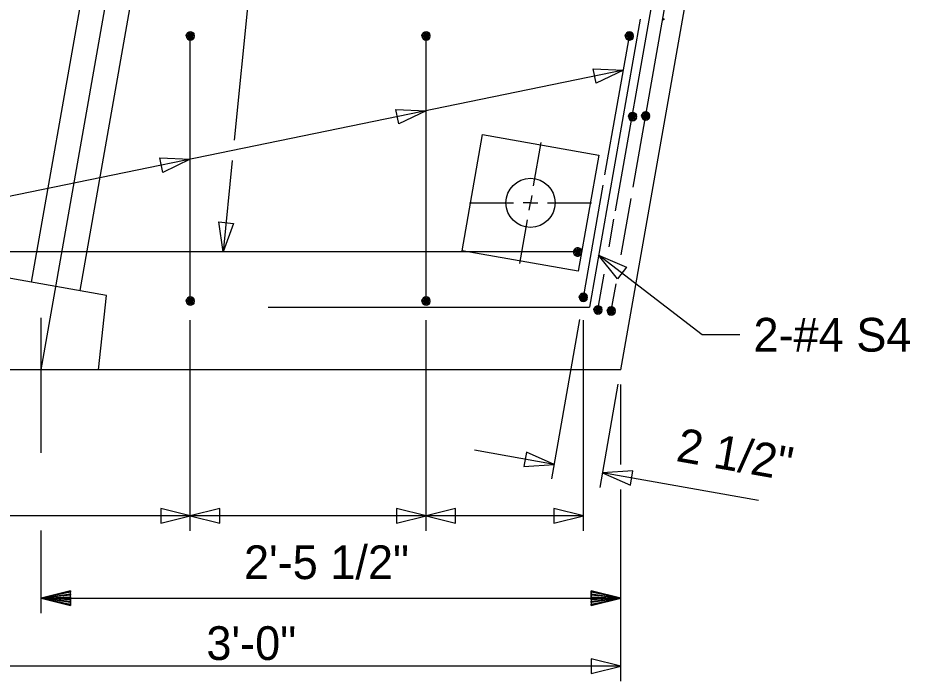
# Model space of a CAD drawing. Extents: x -408 to -23, y -15 to 117.
# Drawn here: x -92.937 to -89.153, y 40.166 to 42.979 of the extents above; entities that cross this region are included whole.
import ezdxf

# ---------------------------------------------------------------- set-up
doc = ezdxf.new("R2010")
doc.units = 0
for name, color, linetype in [('Arrowhead Terminators CELL', 7, 'Continuous'), ('Dimension Lines', 7, 'Continuous'), ('Mis Center Lines', 7, 'Continuous'), ('Rebar Lines', 7, 'Continuous'), ('Sup Concrete Girder Lines', 7, 'Continuous'), ('Sup Cored Slab Unit', 7, 'Continuous'), ('Text', 7, 'Continuous')]:
    doc.layers.add(name, color=color, linetype=linetype)

msp = doc.modelspace()

# ---------------------------------------------------------------- linework, layer by layer
at = {"layer": 'Arrowhead Terminators CELL'}
for points in [[(-90.3692, 42.7573), (-90.4853, 42.7015), (-90.4979, 42.7627)], [(-91.2058, 42.5852), (-91.3219, 42.5294), (-91.3345, 42.5906)], [(-92.2058, 42.3794), (-92.3219, 42.3236), (-92.3345, 42.3848)], [(-92.0665, 41.9859), (-92.0852, 42.1134), (-92.023, 42.1072)], [(-90.4746, 41.9723), (-90.3564, 41.921), (-90.3945, 41.8714)], [(-90.6624, 41.0852), (-90.7801, 41.1377), (-90.7909, 41.0761)], [(-90.4573, 41.049), (-90.3396, 40.9965), (-90.3287, 41.0581)], [(-92.2058, 40.8667), (-92.3308, 40.898), (-92.3308, 40.8355)], [(-92.2058, 40.8667), (-92.0808, 40.8355), (-92.0808, 40.898)], [(-91.2058, 40.8667), (-91.3308, 40.898), (-91.3308, 40.8355)], [(-91.2058, 40.8667), (-91.0808, 40.8355), (-91.0808, 40.898)], [(-90.5391, 40.8667), (-90.6641, 40.898), (-90.6641, 40.8355)], [(-90.3803, 40.229), (-90.5053, 40.2603), (-90.5053, 40.1978)]]:
    msp.add_lwpolyline(points, close=True, dxfattribs=at)
at = {"layer": 'Dimension Lines'}
for p, q in [((-91.905, 43.6051), (-92.0192, 42.4603)), ((-90.7507, 42.2662), (-90.7181, 42.4508)), ((-92.0279, 42.3735), (-92.0665, 41.9859)), ((-91.0224, 42.1942), (-90.8349, 42.1942)), ((-90.6918, 42.1942), (-90.5043, 42.1942)), ((-90.8086, 41.9377), (-90.776, 42.1223)), ((-92.8386, 41.134), (-92.8386, 41.7067)), ((-92.2058, 40.8037), (-92.2058, 41.6974)), ((-91.2058, 40.8037), (-91.2058, 41.6974)), ((-90.6733, 41.0236), (-90.5541, 41.7)), ((-90.5391, 40.8037), (-90.5391, 41.6974)), ((-90.4681, 40.9875), (-90.391, 41.4253)), ((-90.3803, 41.0844), (-90.3803, 41.4234)), ((-90.6624, 41.0852), (-91.0013, 41.145)), ((-89.797, 40.9326), (-90.4573, 41.049)), ((-90.3803, 40.166), (-90.3803, 40.9785)), ((-92.2058, 40.8667), (-93.2058, 40.8667)), ((-91.2058, 40.8667), (-92.2058, 40.8667)), ((-90.5391, 40.8667), (-91.2058, 40.8667)), ((-92.8386, 40.4548), (-92.8386, 40.8042)), ((-92.8386, 40.5178), (-90.3803, 40.5178)), ((-90.3803, 40.229), (-93.3803, 40.229))]:
    msp.add_line(p, q, dxfattribs=at)
for points in [[(-90.3692, 42.7573), (-94.2479, 41.9592), (-94.3499, 41.9592)], [(-90.7578, 42.2251), (-90.7633, 42.1942), (-90.7948, 42.1943)], [(-90.7689, 42.1633), (-90.7633, 42.1942), (-90.7319, 42.1941)], [(-89.876, 41.635), (-90.0352, 41.635), (-90.4746, 41.9723)], [(-92.7136, 40.5178), (-92.7136, 40.5115), (-92.8386, 40.5178), (-92.7136, 40.5053), (-92.7136, 40.499), (-92.8386, 40.5178), (-92.7136, 40.4928), (-92.7136, 40.4865), (-92.8386, 40.5178), (-92.7136, 40.549), (-92.7136, 40.5428), (-92.8386, 40.5178), (-92.7136, 40.5365), (-92.7136, 40.5303), (-92.8386, 40.5178), (-92.7136, 40.524), (-92.7136, 40.4865), (-92.7136, 40.549), (-92.8386, 40.5178), (-92.7136, 40.4865)], [(-90.5053, 40.5178), (-90.5053, 40.524), (-90.3803, 40.5178), (-90.5053, 40.5303), (-90.5053, 40.5365), (-90.3803, 40.5178), (-90.5053, 40.5428), (-90.5053, 40.549), (-90.3803, 40.5178), (-90.5053, 40.4865), (-90.5053, 40.4928), (-90.3803, 40.5178), (-90.5053, 40.499), (-90.5053, 40.5053), (-90.3803, 40.5178), (-90.5053, 40.5115), (-90.5053, 40.549), (-90.5053, 40.4865), (-90.3803, 40.5178), (-90.5053, 40.549)]]:
    msp.add_lwpolyline(points, dxfattribs=at)
at = {"layer": 'Mis Center Lines'}
msp.add_line((-92.8386, 41.4859), (-92.3205, 44.4243), dxfattribs=at)
at = {"layer": 'Rebar Lines'}
for p, q in [((-90.4029, 42.1609), (-90.2165, 43.2181)), ((-90.3283, 42.2602), (-90.1746, 43.1323)), ((-90.2982, 42.9727), (-90.5135, 41.7515)), ((-92.2058, 41.7775), (-92.2058, 42.9025)), ((-92.2058, 42.3526), (-92.2058, 42.9025)), ((-91.2058, 41.7775), (-91.2058, 42.9025)), ((-91.2058, 42.3526), (-91.2058, 42.9025)), ((-90.4476, 42.3127), (-90.3438, 42.9015)), ((-90.5391, 41.7936), (-90.4552, 42.2694)), ((-90.3788, 41.9739), (-90.3368, 42.2123)), ((-90.4299, 42.0075), (-90.4091, 42.1254)), ((-90.5633, 41.9859), (-93.2508, 41.9859)), ((-90.477, 41.7403), (-90.4504, 41.8912)), ((-90.4208, 41.7359), (-90.4005, 41.8506)), ((-91.8758, 41.7515), (-90.5135, 41.7515))]:
    msp.add_line(p, q, dxfattribs=at)
for points in [[(-92.1882, 42.9025), (-92.1895, 42.9092), (-92.1933, 42.915), (-92.199, 42.9188), (-92.2058, 42.9201), (-92.2125, 42.9188), (-92.2183, 42.915), (-92.2221, 42.9093), (-92.2234, 42.9025), (-92.2221, 42.8958), (-92.2183, 42.8901), (-92.2126, 42.8862), (-92.2058, 42.8849), (-92.199, 42.8862), (-92.1934, 42.89), (-92.1895, 42.8957), (-92.1882, 42.9025), (-92.2058, 42.9025), (-92.2234, 42.9025), (-92.2221, 42.9093), (-92.2058, 42.9025), (-92.2183, 42.915), (-92.2125, 42.9188), (-92.2058, 42.9025), (-92.2058, 42.9201), (-92.199, 42.9188), (-92.2058, 42.9025), (-92.1933, 42.915), (-92.1895, 42.9092), (-92.2058, 42.9025), (-92.1895, 42.8957), (-92.1934, 42.89), (-92.2058, 42.9025), (-92.199, 42.8862), (-92.2058, 42.8849), (-92.2058, 42.9025), (-92.2126, 42.8862), (-92.2183, 42.8901), (-92.2058, 42.9025), (-92.2221, 42.8958)], [(-91.1882, 42.9025), (-91.1895, 42.9092), (-91.1933, 42.915), (-91.199, 42.9188), (-91.2058, 42.9201), (-91.2125, 42.9188), (-91.2183, 42.915), (-91.2221, 42.9093), (-91.2234, 42.9025), (-91.2221, 42.8958), (-91.2183, 42.8901), (-91.2126, 42.8862), (-91.2058, 42.8849), (-91.199, 42.8862), (-91.1934, 42.89), (-91.1895, 42.8957), (-91.1882, 42.9025), (-91.2058, 42.9025), (-91.2234, 42.9025), (-91.2221, 42.9093), (-91.2058, 42.9025), (-91.2183, 42.915), (-91.2125, 42.9188), (-91.2058, 42.9025), (-91.2058, 42.9201), (-91.199, 42.9188), (-91.2058, 42.9025), (-91.1933, 42.915), (-91.1895, 42.9092), (-91.2058, 42.9025), (-91.1895, 42.8957), (-91.1934, 42.89), (-91.2058, 42.9025), (-91.199, 42.8862), (-91.2058, 42.8849), (-91.2058, 42.9025), (-91.2126, 42.8862), (-91.2183, 42.8901), (-91.2058, 42.9025), (-91.2221, 42.8958)], [(-90.3262, 42.9015), (-90.3275, 42.9082), (-90.3313, 42.9139), (-90.337, 42.9178), (-90.3438, 42.9191), (-90.3505, 42.9178), (-90.3562, 42.9139), (-90.36, 42.9082), (-90.3614, 42.9015), (-90.36, 42.8948), (-90.3562, 42.889), (-90.3505, 42.8852), (-90.3438, 42.8838), (-90.337, 42.8852), (-90.3313, 42.889), (-90.3275, 42.8947), (-90.3262, 42.9015), (-90.3438, 42.9015), (-90.3614, 42.9015), (-90.36, 42.9082), (-90.3438, 42.9015), (-90.3562, 42.9139), (-90.3505, 42.9178), (-90.3438, 42.9015), (-90.3438, 42.9191), (-90.337, 42.9178), (-90.3438, 42.9015), (-90.3313, 42.9139), (-90.3275, 42.9082), (-90.3438, 42.9015), (-90.3275, 42.8947), (-90.3313, 42.889), (-90.3438, 42.9015), (-90.337, 42.8852), (-90.3438, 42.8838), (-90.3438, 42.9015), (-90.3505, 42.8852), (-90.3562, 42.889), (-90.3438, 42.9015), (-90.36, 42.8948)], [(-90.3127, 42.5604), (-90.314, 42.5671), (-90.3178, 42.5728), (-90.3235, 42.5767), (-90.3303, 42.578), (-90.337, 42.5767), (-90.3427, 42.5728), (-90.3465, 42.5671), (-90.3479, 42.5604), (-90.3465, 42.5537), (-90.3427, 42.5479), (-90.3371, 42.5441), (-90.3303, 42.5427), (-90.3235, 42.5441), (-90.3178, 42.5479), (-90.314, 42.5536), (-90.3127, 42.5604), (-90.3303, 42.5604), (-90.3479, 42.5604), (-90.3465, 42.5671), (-90.3303, 42.5604), (-90.3427, 42.5728), (-90.337, 42.5767), (-90.3303, 42.5604), (-90.3303, 42.578), (-90.3235, 42.5767), (-90.3303, 42.5604), (-90.3178, 42.5728), (-90.314, 42.5671), (-90.3303, 42.5604), (-90.314, 42.5536), (-90.3178, 42.5479), (-90.3303, 42.5604), (-90.3235, 42.5441), (-90.3303, 42.5427), (-90.3303, 42.5604), (-90.3371, 42.5441), (-90.3427, 42.5479), (-90.3303, 42.5604), (-90.3465, 42.5537)], [(-90.2574, 42.5625), (-90.2587, 42.5692), (-90.2625, 42.575), (-90.2683, 42.5788), (-90.275, 42.5801), (-90.2817, 42.5788), (-90.2875, 42.575), (-90.2913, 42.5693), (-90.2926, 42.5625), (-90.2913, 42.5558), (-90.2875, 42.5501), (-90.2818, 42.5462), (-90.275, 42.5449), (-90.2683, 42.5462), (-90.2626, 42.55), (-90.2587, 42.5557), (-90.2574, 42.5625), (-90.275, 42.5625), (-90.2926, 42.5625), (-90.2913, 42.5693), (-90.275, 42.5625), (-90.2875, 42.575), (-90.2817, 42.5788), (-90.275, 42.5625), (-90.275, 42.5801), (-90.2683, 42.5788), (-90.275, 42.5625), (-90.2625, 42.575), (-90.2587, 42.5692), (-90.275, 42.5625), (-90.2587, 42.5557), (-90.2626, 42.55), (-90.275, 42.5625), (-90.2683, 42.5462), (-90.275, 42.5449), (-90.275, 42.5625), (-90.2818, 42.5462), (-90.2875, 42.5501), (-90.275, 42.5625), (-90.2913, 42.5558)], [(-90.546, 41.9828), (-90.5462, 41.9897), (-90.5489, 41.996), (-90.5539, 42.0008), (-90.5603, 42.0032), (-90.5671, 42.0031), (-90.5734, 42.0003), (-90.5782, 41.9954), (-90.5807, 41.989), (-90.5805, 41.9821), (-90.5778, 41.9758), (-90.5729, 41.971), (-90.5664, 41.9685), (-90.5595, 41.9687), (-90.5533, 41.9714), (-90.5485, 41.9764), (-90.546, 41.9828), (-90.5633, 41.9859), (-90.5807, 41.989), (-90.5782, 41.9954), (-90.5633, 41.9859), (-90.5734, 42.0003), (-90.5671, 42.0031), (-90.5633, 41.9859), (-90.5603, 42.0032), (-90.5539, 42.0008), (-90.5633, 41.9859), (-90.5489, 41.996), (-90.5462, 41.9897), (-90.5633, 41.9859), (-90.5485, 41.9764), (-90.5533, 41.9714), (-90.5633, 41.9859), (-90.5595, 41.9687), (-90.5664, 41.9685), (-90.5633, 41.9859), (-90.5729, 41.971), (-90.5778, 41.9758), (-90.5633, 41.9859), (-90.5805, 41.9821)], [(-92.1882, 41.7775), (-92.1895, 41.7842), (-92.1933, 41.79), (-92.199, 41.7938), (-92.2058, 41.7951), (-92.2125, 41.7938), (-92.2183, 41.79), (-92.2221, 41.7843), (-92.2234, 41.7775), (-92.2221, 41.7708), (-92.2183, 41.7651), (-92.2126, 41.7612), (-92.2058, 41.7599), (-92.199, 41.7612), (-92.1934, 41.765), (-92.1895, 41.7707), (-92.1882, 41.7775), (-92.2058, 41.7775), (-92.2234, 41.7775), (-92.2221, 41.7843), (-92.2058, 41.7775), (-92.2183, 41.79), (-92.2125, 41.7938), (-92.2058, 41.7775), (-92.2058, 41.7951), (-92.199, 41.7938), (-92.2058, 41.7775), (-92.1933, 41.79), (-92.1895, 41.7842), (-92.2058, 41.7775), (-92.1895, 41.7707), (-92.1934, 41.765), (-92.2058, 41.7775), (-92.199, 41.7612), (-92.2058, 41.7599), (-92.2058, 41.7775), (-92.2126, 41.7612), (-92.2183, 41.7651), (-92.2058, 41.7775), (-92.2221, 41.7708)], [(-91.1882, 41.7775), (-91.1895, 41.7842), (-91.1933, 41.79), (-91.199, 41.7938), (-91.2058, 41.7951), (-91.2125, 41.7938), (-91.2183, 41.79), (-91.2221, 41.7843), (-91.2234, 41.7775), (-91.2221, 41.7708), (-91.2183, 41.7651), (-91.2126, 41.7612), (-91.2058, 41.7599), (-91.199, 41.7612), (-91.1934, 41.765), (-91.1895, 41.7707), (-91.1882, 41.7775), (-91.2058, 41.7775), (-91.2234, 41.7775), (-91.2221, 41.7843), (-91.2058, 41.7775), (-91.2183, 41.79), (-91.2125, 41.7938), (-91.2058, 41.7775), (-91.2058, 41.7951), (-91.199, 41.7938), (-91.2058, 41.7775), (-91.1933, 41.79), (-91.1895, 41.7842), (-91.2058, 41.7775), (-91.1895, 41.7707), (-91.1934, 41.765), (-91.2058, 41.7775), (-91.199, 41.7612), (-91.2058, 41.7599), (-91.2058, 41.7775), (-91.2126, 41.7612), (-91.2183, 41.7651), (-91.2058, 41.7775), (-91.2221, 41.7708)], [(-90.5215, 41.7936), (-90.5228, 41.8003), (-90.5266, 41.806), (-90.5324, 41.8099), (-90.5391, 41.8112), (-90.5459, 41.8099), (-90.5516, 41.806), (-90.5554, 41.8003), (-90.5567, 41.7936), (-90.5554, 41.7868), (-90.5516, 41.7811), (-90.5459, 41.7773), (-90.5391, 41.7759), (-90.5324, 41.7773), (-90.5267, 41.7811), (-90.5228, 41.7868), (-90.5215, 41.7936), (-90.5391, 41.7936), (-90.5567, 41.7936), (-90.5554, 41.8003), (-90.5391, 41.7936), (-90.5516, 41.806), (-90.5459, 41.8099), (-90.5391, 41.7936), (-90.5391, 41.8112), (-90.5324, 41.8099), (-90.5391, 41.7936), (-90.5266, 41.806), (-90.5228, 41.8003), (-90.5391, 41.7936), (-90.5228, 41.7868), (-90.5267, 41.7811), (-90.5391, 41.7936), (-90.5324, 41.7773), (-90.5391, 41.7759), (-90.5391, 41.7936), (-90.5459, 41.7773), (-90.5516, 41.7811), (-90.5391, 41.7936), (-90.5554, 41.7868)], [(-90.4594, 41.7403), (-90.4607, 41.747), (-90.4645, 41.7528), (-90.4702, 41.7566), (-90.477, 41.7579), (-90.4837, 41.7566), (-90.4895, 41.7528), (-90.4933, 41.7471), (-90.4946, 41.7403), (-90.4933, 41.7336), (-90.4895, 41.7279), (-90.4838, 41.724), (-90.477, 41.7227), (-90.4702, 41.724), (-90.4646, 41.7278), (-90.4607, 41.7336), (-90.4594, 41.7403), (-90.477, 41.7403), (-90.4946, 41.7403), (-90.4933, 41.7471), (-90.477, 41.7403), (-90.4895, 41.7528), (-90.4837, 41.7566), (-90.477, 41.7403), (-90.477, 41.7579), (-90.4702, 41.7566), (-90.477, 41.7403), (-90.4645, 41.7528), (-90.4607, 41.747), (-90.477, 41.7403), (-90.4607, 41.7336), (-90.4646, 41.7278), (-90.477, 41.7403), (-90.4702, 41.724), (-90.477, 41.7227), (-90.477, 41.7403), (-90.4838, 41.724), (-90.4895, 41.7279), (-90.477, 41.7403), (-90.4933, 41.7336)], [(-90.4032, 41.7359), (-90.4045, 41.7426), (-90.4083, 41.7483), (-90.414, 41.7522), (-90.4208, 41.7535), (-90.4275, 41.7522), (-90.4332, 41.7483), (-90.437, 41.7427), (-90.4384, 41.7359), (-90.437, 41.7292), (-90.4332, 41.7234), (-90.4275, 41.7196), (-90.4208, 41.7182), (-90.414, 41.7196), (-90.4083, 41.7234), (-90.4045, 41.7291), (-90.4032, 41.7359), (-90.4208, 41.7359), (-90.4384, 41.7359), (-90.437, 41.7427), (-90.4208, 41.7359), (-90.4332, 41.7483), (-90.4275, 41.7522), (-90.4208, 41.7359), (-90.4208, 41.7535), (-90.414, 41.7522), (-90.4208, 41.7359), (-90.4083, 41.7483), (-90.4045, 41.7426), (-90.4208, 41.7359), (-90.4045, 41.7291), (-90.4083, 41.7234), (-90.4208, 41.7359), (-90.414, 41.7196), (-90.4208, 41.7182), (-90.4208, 41.7359), (-90.4275, 41.7196), (-90.4332, 41.7234), (-90.4208, 41.7359), (-90.437, 41.7292)]]:
    msp.add_lwpolyline(points, dxfattribs=at)
at = {"layer": 'Sup Concrete Girder Lines'}
for p, q in [((-92.8788, 41.8582), (-92.4154, 44.4859)), ((-92.6736, 41.822), (-92.2039, 44.4859)), ((-90.3803, 41.4859), (-89.8622, 44.4243)), ((-90.3803, 41.4859), (-94.1237, 41.4859))]:
    msp.add_line(p, q, dxfattribs=at)
msp.add_lwpolyline([(-92.5953, 41.4859), (-92.5607, 41.8021), (-92.9916, 41.878), (-93.0819, 41.4859)], dxfattribs=at)
for centre, radius in [((-90.1996, 42.9727), 0.00273), ((-90.7633, 42.1942), 0.1042)]:
    msp.add_circle(centre, radius, dxfattribs=at)
at = {"layer": 'Sup Cored Slab Unit'}
msp.add_lwpolyline([(-90.9661, 42.4838), (-90.4737, 42.397), (-90.5605, 41.9046), (-91.0529, 41.9914)], close=True, dxfattribs=at)

# ---------------------------------------------------------------- texts
at = {"layer": 'Text'}
for s, p in [('2-#4 S4', (-89.8174, 41.5635)), ('2\'-5 1/2"', (-91.9782, 40.5988)), ('3\'-0"', (-92.1376, 40.2558))]:
    msp.add_text(s, height=0.14302, dxfattribs=at).set_placement(p)
msp.add_text('2 1/2"', height=0.14302, rotation=349.9998, dxfattribs=at).set_placement((-90.1503, 41.1002))

doc.saveas('drawing.dxf')
